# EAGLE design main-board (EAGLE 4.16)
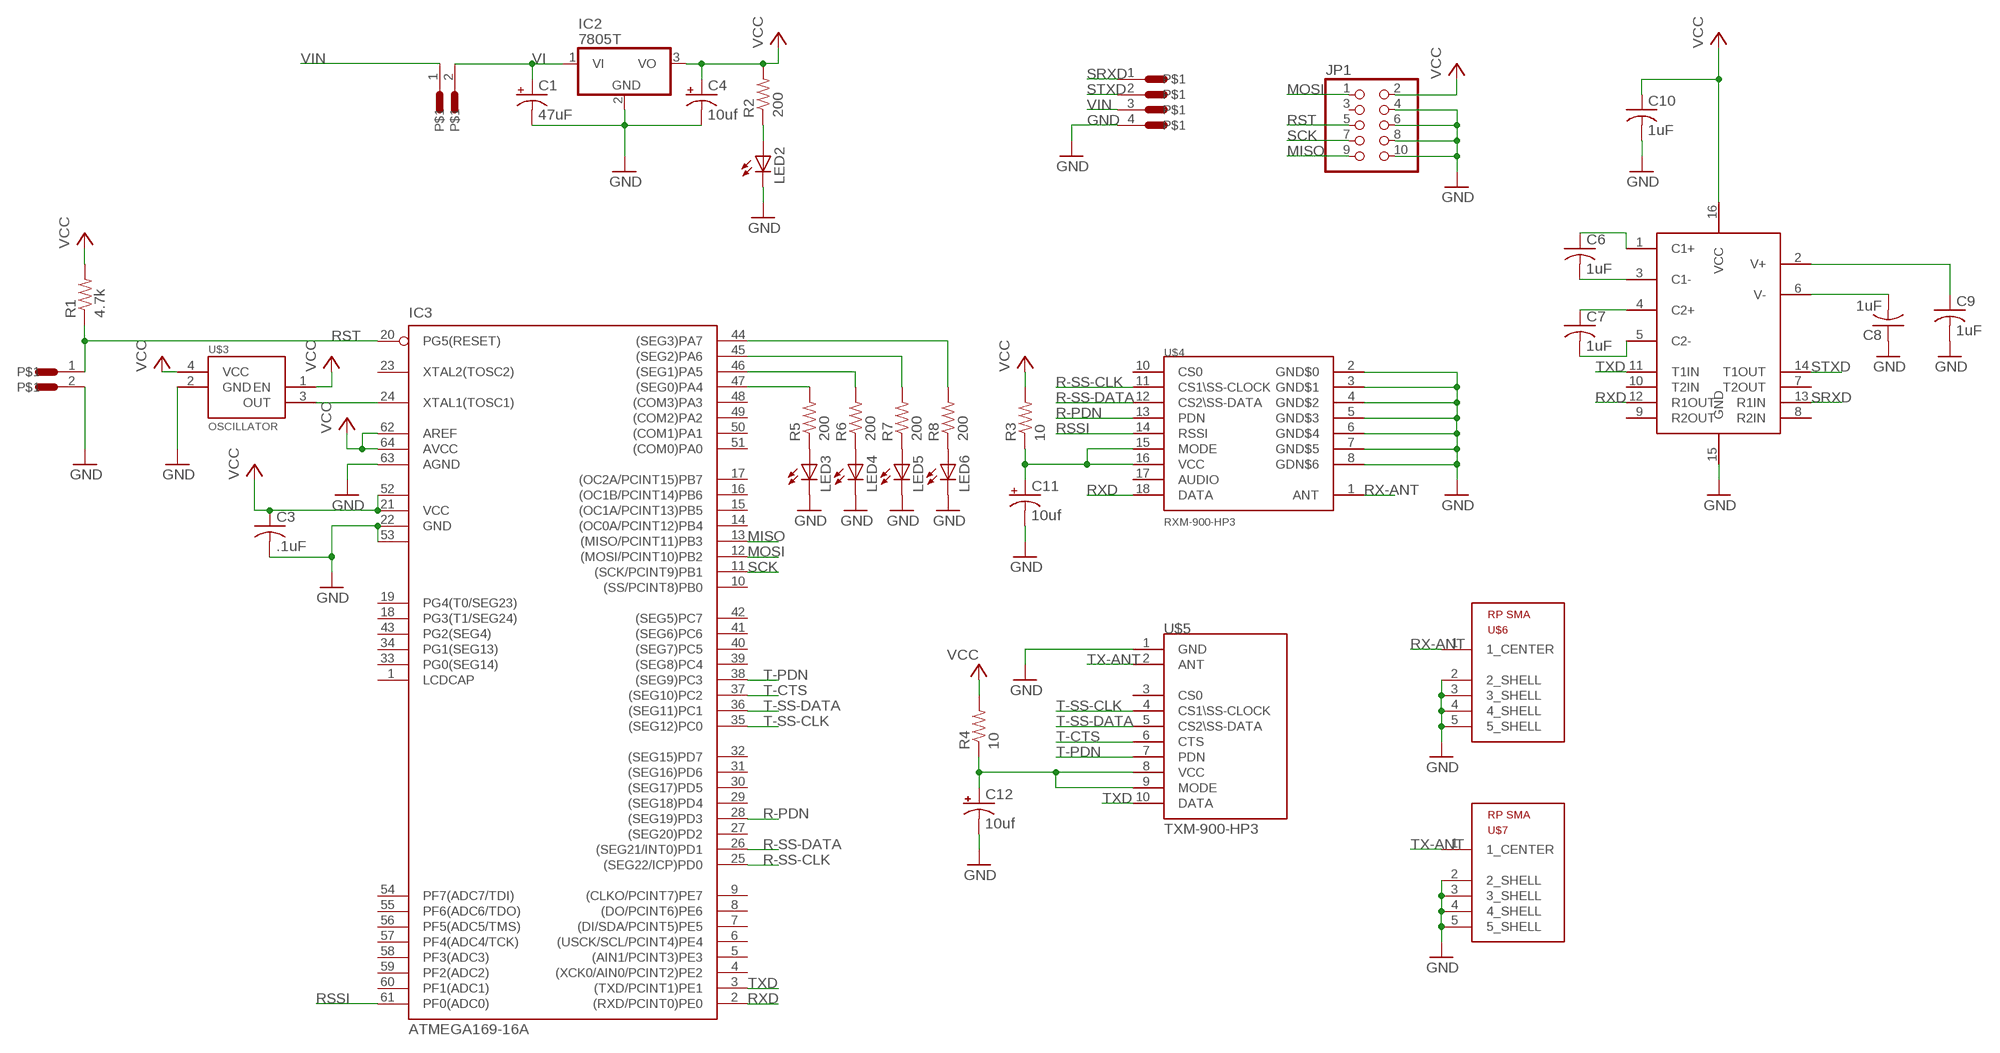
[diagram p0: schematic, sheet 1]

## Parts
C1  47uF  CPOL-USE  [PANASONIC_E]
C3  .1uF  C-USC0603  [C0603]
C4  10uf  CPOL-USB  [PANASONIC_B]
C6  1uF  C-USC0603  [C0603]
C7  1uF  C-USC0603  [C0603]
C8  1uF  C-USC0603  [C0603]
C9  1uF  C-USC0603  [C0603]
C10  1uF  C-USC0603  [C0603]
C11  10uf  CPOL-USB  [PANASONIC_B]
C12  10uf  CPOL-USB  [PANASONIC_B]
IC2  7805T  [TO220H]
IC3  ATMEGA169-16A  [TQFP64]
JP1  PINHD-2X5  [2X05]
LED2  LED5MM  [LED5MM]
LED3  LED5MM  [LED5MM]
LED4  LED5MM  [LED5MM]
LED5  LED5MM  [LED5MM]
LED6  LED5MM  [LED5MM]
R1  4.7k  R-US_R0603  [R0603]
R2  200  R-US_R0603  [R0603]
R3  10  R-US_R0603  [R0603]
R4  10  R-US_R0603  [R0603]
R5  200  R-US_R0603  [R0603]
R6  200  R-US_R0603  [R0603]
R7  200  R-US_R0603  [R0603]
R8  200  R-US_R0603  [R0603]
U$1  JST_PA_2  [JST_PA_2]
U$2  JST_PA_2  [JST_PA_2]
U$3  OSCILLATOR  [7X5MM]
U$4  RXM-900-HP3  [RXM-900-HP3]
U$5  TXM-900-HP3  [TXM-900-HP3]
U$6  RP_SMA_TH  [RPSMA_TH]
U$7  RP_SMA_TH  [RPSMA_TH]
U$8  JST_PA_4  [JST_PA_4]
U$9  MAX232-SO16  [SO16]

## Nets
GND: C1.- C3.2 C4.- C8.1 C9.2 C10.2 C11.- C12.- IC2.2(GND) IC3.22(GND) IC3.53(GND1) IC3.63(AGND) JP1.4 JP1.6 JP1.8 JP1.10 LED2.K(C) LED3.K(C) LED4.K(C) LED5.K(C) LED6.K(C) U$1.2 U$3.2(GND) U$4.2(GND$0) U$4.3(GND$1) U$4.4(GND$2) U$4.5(GND$3) U$4.6(GND$4) U$4.7(GND$5) U$4.8(GDN$6) U$5.1(GND) U$6.2(2_SHELL) U$6.3(3_SHELL) U$6.4(4_SHELL) U$6.5(5_SHELL) U$7.2(2_SHELL) U$7.3(3_SHELL) U$7.4(4_SHELL) U$7.5(5_SHELL) U$8.4 U$9.15(GND)
MISO: IC3.13((MISO/PCINT11)PB3) JP1.9
MOSI: IC3.12((MOSI/PCINT10)PB2) JP1.1
N$1: LED2.A R2.1
N$2: C6.1 U$9.1(C1+)
N$3: C6.2 U$9.3(C1-)
N$4: C7.1 U$9.4(C2+)
N$5: C7.2 U$9.5(C2-)
N$6: C9.1 U$9.2(V+)
N$7: C8.2 U$9.6(V-)
N$8: LED3.A R5.1
N$9: C12.+ R4.1 U$5.8(VCC) U$5.9(MODE)
N$10: LED4.A R6.1
N$11: LED5.A R7.1
N$12: C11.+ R3.1 U$4.15(MODE) U$4.16(VCC)
N$13: LED6.A R8.1
N$14: IC3.47((SEG0)PA4) R5.2
N$15: IC3.46((SEG1)PA5) R6.2
N$16: IC3.45((SEG2)PA6) R7.2
N$17: IC3.44((SEG3)PA7) R8.2
N$18: IC3.24(XTAL1(TOSC1)) U$3.3(OUT)
R-PDN: IC3.28((SEG19)PD3) U$4.13(PDN)
R-SS-CLK: IC3.25((SEG22/ICP)PD0) U$4.11(CS1\SS-CLOCK)
R-SS-DATA: IC3.26((SEG21/INT0)PD1) U$4.12(CS2\SS-DATA)
RSSI: IC3.61(PF0(ADC0)) U$4.14(RSSI)
RST: IC3.20(PG5(RESET)) JP1.5 R1.1 U$1.1
RX-ANT: U$4.1(ANT) U$6.1(1_CENTER)
RXD: IC3.2((RXD/PCINT0)PE0) U$4.18(DATA) U$9.12(R1OUT)
SCK: IC3.11((SCK/PCINT9)PB1) JP1.7
SRXD: U$8.1 U$9.13(R1IN)
STXD: U$8.2 U$9.14(T1OUT)
T-CTS: IC3.37((SEG10)PC2) U$5.6(CTS)
T-PDN: IC3.38((SEG9)PC3) U$5.7(PDN)
T-SS-CLK: IC3.35((SEG12)PC0) U$5.4(CS1\SS-CLOCK)
T-SS-DATA: IC3.36((SEG11)PC1) U$5.5(CS2\SS-DATA)
TX-ANT: U$5.2(ANT) U$7.1(1_CENTER)
TXD: IC3.3((TXD/PCINT1)PE1) U$5.10(DATA) U$9.11(T1IN)
VCC: C3.1 C4.+ C10.1 IC2.3(VO) IC3.21(VCC) IC3.52(VCC1) IC3.62(AREF) IC3.64(AVCC) JP1.2 R1.2 R2.2 R3.2 R4.2 U$3.1(EN) U$3.4(VCC) U$9.16(VCC)
VI: C1.+ IC2.1(VI) U$2.2
VIN: U$2.1 U$8.3
Unconnected: IC3.1(LCDCAP) IC3.4((XCK0/AIN0/PCINT2)PE2) IC3.5((AIN1/PCINT3)PE3) IC3.6((USCK/SCL/PCINT4)PE4) IC3.7((DI/SDA/PCINT5)PE5) IC3.8((DO/PCINT6)PE6) IC3.9((CLKO/PCINT7)PE7) IC3.10((SS/PCINT8)PB0) IC3.14((OC0A/PCINT12)PB4) IC3.15((OC1A/PCINT13)PB5) IC3.16((OC1B/PCINT14)PB6) IC3.17((OC2A/PCINT15)PB7) IC3.18(PG3(T1/SEG24)) IC3.19(PG4(T0/SEG23)) IC3.23(XTAL2(TOSC2)) IC3.27((SEG20)PD2) IC3.29((SEG18)PD4) IC3.30((SEG17)PD5) IC3.31((SEG16)PD6) IC3.32((SEG15)PD7) IC3.33(PG0(SEG14)) IC3.34(PG1(SEG13)) IC3.39((SEG8)PC4) IC3.40((SEG7)PC5) IC3.41((SEG6)PC6) IC3.42((SEG5)PC7) IC3.43(PG2(SEG4)) IC3.48((COM3)PA3) IC3.49((COM2)PA2) IC3.50((COM1)PA1) IC3.51((COM0)PA0) IC3.54(PF7(ADC7/TDI)) IC3.55(PF6(ADC6/TDO)) IC3.56(PF5(ADC5/TMS)) IC3.57(PF4(ADC4/TCK)) IC3.58(PF3(ADC3)) IC3.59(PF2(ADC2)) IC3.60(PF1(ADC1)) JP1.3 U$4.10(CS0) U$4.17(AUDIO) U$5.3(CS0) U$9.7(T2OUT) U$9.8(R2IN) U$9.9(R2OUT) U$9.10(T2IN)

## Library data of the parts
C1 C4 C11 C12 = rcl:CPOL-US: POLARIZED CAPACITOR, American symbol
C3 C6-C10 = rcl:C-US: CAPACITOR, American symbol
IC2 = linear:78*: Positive VOLTAGE REGULATOR Source: http://cache.national.com/ds/LM/LM78L05.pdf http://www.fairchildsemi.com/ds/LM/LM7805.pdf
IC3 = avr:ATMEGA169: MICROCONTROLLER 16 Kbytes FLASH 1 Kbytes SRAM 512 bytes EEPROM USART 8-channel 10 bit ADC 4x25 Segment LCD Driver
JP1 = pinhead:PINHD-2X5: PIN HEADER
LED2-LED6 = led:LED: LED
R1-R8 = rcl:R-US_: RESISTOR, American symbol
U$1 U$2 = jst_pa:JST_PA_2
U$3 = misc-personal:OSCILLATOR
U$4 = HP3:RXM-900-HP3
U$5 = HP3:TXM-900-HP3
U$6 U$7 = linx:RP_SMA_TH
U$8 = jst_pa:JST_PA_4
U$9 = max232:MAX232-SO16

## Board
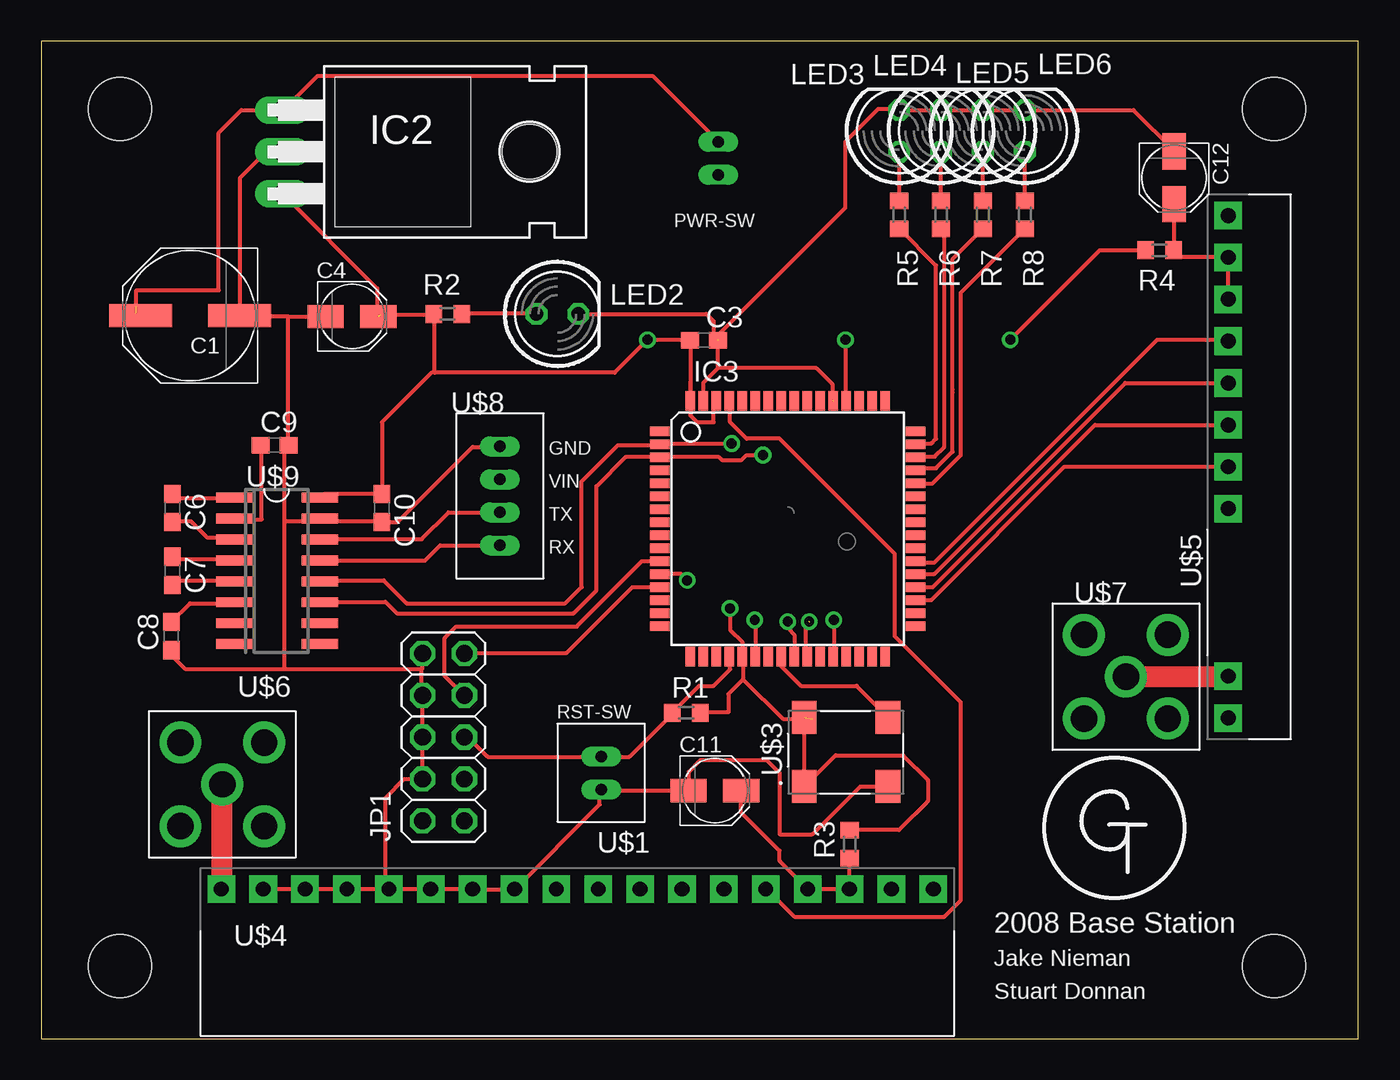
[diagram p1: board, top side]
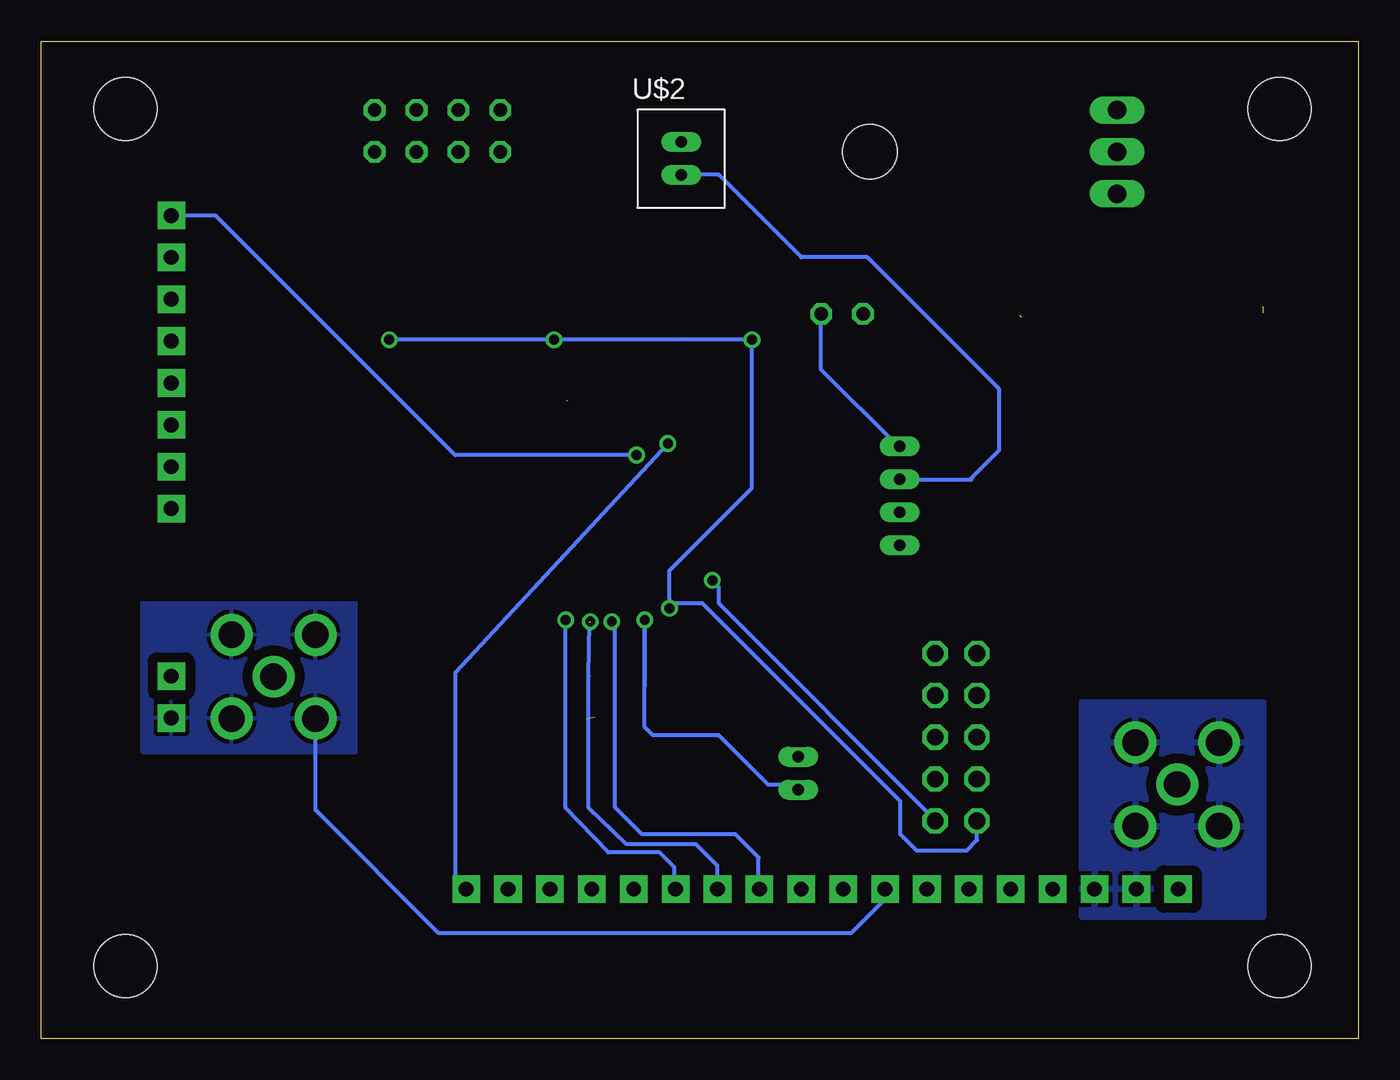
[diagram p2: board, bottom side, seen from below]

Size 79.87 x 60.49 mm. Coordinates in mm from the lower left corner, seen from the top.
Outline: 0,0 79.87,0 79.87,60.49 0,60.49 0,0
Copper layers (1*16): Top 0.035mm / dielectric 1.5mm / Bottom 0.035mm
Design rules "4pcb": minimum track width 6mil, minimum drill 15mil, track to track 6mil, track to pad 6mil, pad to pad 6mil, via to via 6mil, smd to smd 6mil, copper to edge 40mil, drill to drill 6mil, minimum pad ring 10mil, minimum via ring 8mil, stop-mask expansion 6mil, vias tented up to drill 0mil, thermal gap 10mil
Holes 3.82 mm at 4.77,56.39 4.77,4.39 74.77,4.39 74.77,56.39

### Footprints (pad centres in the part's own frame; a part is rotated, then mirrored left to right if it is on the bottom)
PANASONIC_E = smd 3.8 x 1.4: + 3,0; - -3,0
C0603 = smd 1.1 x 1: 1 -0.85,0; 2 0.85,0
PANASONIC_B = smd 2.2 x 1.4: + 1.6,0; - -1.6,0
TO220H = drill 1.118 long: 1 -2.54,-10.16; 2 0,-10.16; 3 2.54,-10.16 | hole 3.302: 0,4.826
TQFP64 = smd 1.194 x 0.559: 1 -7.76,5.905; 2 -7.76,5.118; 3 -7.76,4.331; 4 -7.76,3.543; 5 -7.76,2.756; 6 -7.76,1.968; 7 -7.76,1.181; 8 -7.76,0.394; 9 -7.76,-0.394; 10 -7.76,-1.181; 11 -7.76,-1.968; 12 -7.76,-2.756; 13 -7.76,-3.543; 14 -7.76,-4.331; 15 -7.76,-5.118; 16 -7.76,-5.905; 33 7.76,-5.905; 34 7.76,-5.118; 35 7.76,-4.331; 36 7.76,-3.543; 37 7.76,-2.756; 38 7.76,-1.968; 39 7.76,-1.181; 40 7.76,-0.394; 41 7.76,0.394; 42 7.76,1.181; 43 7.76,1.968; 44 7.76,2.756; 45 7.76,3.543; 46 7.76,4.331; 47 7.76,5.118; 48 7.76,5.905 | smd 0.559 x 1.194: 17 -5.905,-7.76; 18 -5.118,-7.76; 19 -4.331,-7.76; 20 -3.543,-7.76; 21 -2.756,-7.76; 22 -1.968,-7.76; 23 -1.181,-7.76; 24 -0.394,-7.76; 25 0.394,-7.76; 26 1.181,-7.76; 27 1.968,-7.76; 28 2.756,-7.76; 29 3.543,-7.76; 30 4.331,-7.76; 31 5.118,-7.76; 32 5.905,-7.76; 49 5.905,7.76; 50 5.118,7.76; 51 4.331,7.76; 52 3.543,7.76; 53 2.756,7.76; 54 1.968,7.76; 55 1.181,7.76; 56 0.394,7.76; 57 -0.394,7.76; 58 -1.181,7.76; 59 -1.968,7.76; 60 -2.756,7.76; 61 -3.543,7.76; 62 -4.331,7.76; 63 -5.118,7.76; 64 -5.905,7.76
2X05 = drill 1.016 octagon: 1 -5.08,-1.27; 2 -5.08,1.27; 3 -2.54,-1.27; 4 -2.54,1.27; 5 0,-1.27; 6 0,1.27; 7 2.54,-1.27; 8 2.54,1.27; 9 5.08,-1.27; 10 5.08,1.27
LED5MM = drill 0.813 octagon: A -1.27,0; K 1.27,0
R0603 = smd 1 x 1.1: 1 -0.85,0; 2 0.85,0
JST_PA_2 = drill 0.7 long: 1 13.35,0; 2 11.35,0
7X5MM = smd 1.5 x 2: 1 0,-4.2; 2 5.08,-4.2; 3 5.08,0; 4 0,0
RXM-900-HP3 = drill 0.9 pad 1.676 square: 1 0,0; 2 2.54,0; 3 5.08,0; 4 7.62,0; 5 10.16,0; 6 12.7,0; 7 15.24,0; 8 17.78,0; 9 20.32,0; 10 22.86,0; 11 25.4,0; 12 27.94,0; 13 30.48,0; 14 33.02,0; 15 35.56,0; 16 38.1,0; 17 40.64,0; 18 43.18,0
TXM-900-HP3 = drill 0.9 pad 1.676 square: 1 0,0; 2 2.54,0; 3 12.7,0; 4 15.24,0; 5 17.78,0; 6 20.32,0; 7 22.86,0; 8 25.4,0; 9 27.94,0; 10 30.48,0
RPSMA_TH = drill 1.6 pad 2.54 round: 1 0,0; 2 2.54,2.54; 3 2.54,-2.54; 4 -2.54,-2.54; 5 -2.54,2.54
JST_PA_4 = drill 0.7 long: 1 3,0; 2 1,0; 3 -1,0; 4 -3,0
SO16 = smd 0.6 x 2.2: 1 -4.445,-2.6; 2 -3.175,-2.6; 3 -1.905,-2.6; 4 -0.635,-2.6; 5 0.635,-2.6; 6 1.905,-2.6; 7 3.175,-2.6; 8 4.445,-2.6; 9 4.445,2.6; 10 3.175,2.6; 11 1.905,2.6; 12 0.635,2.6; 13 -0.635,2.6; 14 -1.905,2.6; 15 -3.175,2.6; 16 -4.445,2.6

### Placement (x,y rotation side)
C1  9.03,43.85 180 top
C3  40.19,42.35 0 top
C4  18.85,43.8 0 top
C6  7.95,32.18 270 top
C7  7.95,28.37 270 top
C8  7.89,24.41 90 top
C9  14.16,35.99 0 top
C10  20.65,32.18 270 top
C11  40.85,15.04 0 top
C12  68.7,52.21 270 top
IC2  24.79,53.78 270 top
IC3  45.27,30.92 0 top
JP1  24.39,18.28 90 top
LED2  31.3,43.95 0 top
LED3  52.03,55.05 90 top
LED4  54.57,55.05 90 top
LED5  57.11,55.05 90 top
LED6  59.65,55.05 90 top
R1  39.11,19.76 0 top
R2  24.65,43.95 180 top
R3  49.03,11.79 90 top
R4  67.81,47.81 180 top
R5  52.03,49.97 270 top
R6  54.57,49.97 270 top
R7  57.11,49.97 270 top
R8  59.65,49.97 270 top
U$1  33.96,3.74 90 top
U$2  41.06,65.74 270 bottom
U$3  46.27,19.49 0 top
U$4  10.92,9.07 0 top
U$5  71.98,19.44 90 top
U$6  10.98,15.42 180 top
U$7  65.78,21.95 0 top
U$8  27.82,32.92 270 top
U$9  14.3,28.37 270 top

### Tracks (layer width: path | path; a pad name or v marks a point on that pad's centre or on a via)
GND  (via drill 0.6)  (2 unrouted)
  Top 0.254: LED3.K 51.7,56.32 | 40.77,42.39 40.81,42.35 | IC3.63 40.17,38.7 40.17,39.79 41.07,40.69 | 47.97,38.74 47.97,39.69 46.97,40.69 41.07,40.69 | 23.62,9.04 23.57,8.99 | 23.62,9.04 U$4.6 21.15,9.07 21.08,9 | 23.62,9.04 23.65,9.07 U$4.7 26.09,9.07 | U$4.4 18.49,9.07 18.47,9.09 | U$4.4 U$4.5 21.08,9 | U$4.3 U$4.4 | U$4.3 15.97,9.09 | 14.77,31.39 16.75,31.39 U$9.15 16.77,31.41 16.77,31.39 20.59,31.39 C10.2 21.61,31.33 26.17,35.89 27.97,35.89 27.94,35.92 U$8.4 | 14.77,22.39 14.77,31.39 | C8.1 7.77,23.44 7.77,23.39 8.77,22.39 14.77,22.39 | 14.77,31.39 14.77,35.83 C9.2 14.97,35.99 14.97,43.8 | U$4.2 | U$4.2 U$4.3 | U$4.2 13.47,8.99 | LED2.K 40.33,43.95 40.77,43.51 40.77,42.39 | LED5.K 56.84,56.32 56.77,56.39 | LED5.K LED6.K 59.7,56.32 59.77,56.39 59.84,56.32 66.24,56.32 68.7,53.86 C12.- | LED5.K 54.84,56.32 54.77,56.39 54.7,56.32 LED4.K LED3.K | LED3.K 51.84,56.32 51.77,56.39 | 40.77,42.39 48.77,50.39 48.77,54.39 50.77,56.39 51.77,56.39 | 51.77,56.39 51.96,56.39 LED3.K | 40.77,42.39 41,42.39 | 33.92,15.04 U$1.2 | 33.92,15.04 C11.- 39.25,15.01 39.27,14.99 39.27,16.18 39.98,16.89 43.99,16.89 44.77,16.11 44.77,12.39 46.77,12.39 49.67,15.29 U$3.2 | 33.92,15.04 33.87,14.99 33.87,14.19 28.7,9.02 | 26.09,9.07 26.07,9.09 | 26.09,9.07 26.1,9.06 U$4.8 28.7,9.02 | 28.7,9.02 28.67,8.99 | JP1.6 23.12,18.24 23.07,18.19 | JP1.6 JP1.8 23.1,20.82 23.07,20.79 23.07,22.39 | JP1.6 23.12,18.04 23.17,17.99 23.12,17.94 JP1.4 22.02,15.74 20.87,14.59 20.87,9.19 21.07,8.99 21.08,9 | 23.07,22.39 14.77,22.39 | JP1.10 23.12,22.44 23.07,22.39 | 12.07,43.79 12.03,43.83 C1.- 11.98,43.8 | 12.07,43.79 12.07,52.22 13.63,53.78 IC2.2 | 12.07,43.79 12.17,43.69
  Top 0.254: 14.97,43.8 11.98,43.8 | 14.97,43.8 C4.- | 11.98,43.8 11.97,43.79 | C3.2 41.04,40.72 41.07,40.69 | IC3.22 43.3,25.36 v43.27,25.39
  Bottom 0.254: 43.27,21.39 v43.27,25.39 43.27,18.89 42.77,18.39 38.77,18.39 35.77,15.39 34.27,15.39 U$1.2 | U$8.4 27.84,35.92 27.87,35.89 32.57,40.59 LED2.K | U$7.4 63.24,13.86 55.77,6.39 30.77,6.39 28.77,8.39 28.77,9.39 28.7,9.32 U$4.8
  pour Bottom (isolate 0.61): 60.77,26.39 73.77,26.39 73.77,17.39 60.77,17.39
  pour Bottom (isolate 0.61): 5.77,20.39 16.77,20.39 16.77,7.39 5.77,7.39
MISO
  Top 0.254: IC3.13 35.86,27.38 31.87,23.39 25.87,23.39 25.67,23.19 25.66,23.2 JP1.9
MOSI  (via drill 0.6)
  Top 0.254: v39.17,27.79 38.77,28.19 37.77,28.19 37.67,28.09 37.6,28.16 IC3.12
  Bottom 0.254: JP1.1 25.66,13.28 38.77,26.39 38.77,27.39 v39.17,27.79
N$1
  Top 0.254: R2.1 25.47,43.98 25.47,43.99 29.99,43.99 LED2.A
N$2
  Top 0.254: C6.1 7.97,33.01 7.97,32.79 11.67,32.79 U$9.1
N$3
  Top 0.254: U$9.3 11.58,30.39 10.07,30.39 9.07,31.39 7.89,31.39 | 7.89,31.39 7.77,31.39 | C6.2 7.89,31.39
N$4
  Top 0.254: C7.1 8.08,29.09 11.62,29.09 U$9.4
N$5
  Top 0.254: C7.2 8.07,27.64 8.07,27.79 11.64,27.79 U$9.5
N$6
  Top 0.254: C9.1 13.37,35.53 13.37,31.49 11.67,31.49 11.67,31.52 U$9.2
N$7
  Top 0.254: U$9.6 11.77,26.39 9.02,26.39 C8.2
N$8
  Top 0.254: R5.1 52.07,50.79 | R5.1 | LED3.A R5.1
N$9
  Top 0.254: 68.66,47.5 68.77,47.39 71.77,47.39 71.78,47.38 U$5.9 71.98,44.8 | 68.66,47.5 R4.1 68.67,47.79 68.7,47.82 C12.+ | 68.66,47.5 68.65,47.51 | U$5.8 71.98,44.8 | 71.98,44.8 71.97,44.79
N$10
  Top 0.254: 54.48,53.78 54.47,53.79 | 54.48,53.78 LED4.A | R6.1 54.57,53.69 54.48,53.78
N$11
  Top 0.254: R7.1 57.17,50.89 57.11,50.95 LED5.A
N$12
  Top 0.254: C11.+ 42.45,13.71 44.77,11.39 44.77,10.79 U$4.15 48.95,9.07 48.97,9.09 48.99,9.07 U$4.16 49.02,10.84 48.97,10.89 R3.1
N$13
  Top 0.254: R8.1 59.65,50.87 59.67,50.89 59.65,50.91 LED6.A
N$14
  Top 0.254: IC3.47 53.03,36.09 53.97,36.09 54.27,36.39 54.27,46.88 R5.2
N$15
  Top 0.254: 53.17,35.29 53.03,35.15 IC3.46 53.07,35.29 54.17,35.29 54.77,35.89 54.77,48.89 54.57,49.09 R6.2
N$16
  Top 0.254: 55.27,39.19 55.27,35.59 54.27,34.59 53.17,34.59 53.04,34.46 IC3.45 | 55.27,39.19 55.27,39.39 | R7.2 55.27,47.28 55.27,39.19
N$17
  Top 0.254: 52.97,33.59 53.03,33.65 IC3.44 54.06,33.68 55.77,35.39 55.77,39.39 | 55.77,39.39 55.77,39.79 | R8.2 55.77,45.24 55.77,39.39
N$18
  Top 0.254: U$3.3 49.45,21.39 46.07,21.39 44.87,22.59 44.87,22.99 44.97,23.09 44.9,23.16 IC3.24
R-PDN  (via drill 0.6)
  Top 0.254: IC3.28 48.07,23.2 v48.07,25.39
  Bottom 0.254: U$4.13 41.42,9.09 41.47,9.09 41.47,10.39 42.37,11.29 45.47,11.29 48.07,13.99 v48.07,25.39
R-SS-CLK  (via drill 0.6)
  Top 0.254: IC3.25 45.67,24.49 45.27,24.89 v45.27,25.29
  Bottom 0.254: 36.37,9.02 36.37,8.99 | U$4.11 36.37,9.02 | 36.37,9.02 36.37,10.99 37.77,12.39 43.43,12.39 45.07,14.03 45.07,25.09 v45.27,25.29
R-SS-DATA  (via drill 0.6)  (1 unrouted)
  Top 0.254: IC3.26 46.37,23.24 46.37,25.19 46.47,25.29 v46.57,25.29
  Bottom 0.254: U$4.12 38.87,10.49 40.17,11.79 44.37,11.79 46.67,13.99 46.67,21.99 46.62,25.24
RSSI
  Top 0.254: IC3.61 41.77,38.64 41.77,37.39 42.77,36.39 44.77,36.39 51.77,29.39 51.77,24.39 55.77,20.39 55.77,8.39 54.77,7.39 45.67,7.39 43.97,9.09 U$4.14
RST
  Top 0.254: 41.77,23.2 41.77,23.39 | 41.77,23.2 IC3.20 | 41.77,23.2 41.77,22.39 40.77,21.39 39.89,21.39 R1.1 38.26,19.7 38.27,19.69 35.67,17.09 U$1.1 27.07,17.09 25.77,18.39 JP1.5
RX-ANT
  Top 1.27: U$4.1 10.97,9.07 U$6.1
RXD  (via drill 0.6)
  Top 0.254: v41.87,36.09 37.56,36.09 IC3.2 37.56,35.99 | 16.95,27.79 U$9.12 16.9,27.82 16.97,27.89 17.07,27.79 20.77,27.79 22.17,26.39 31.77,26.39 32.77,27.39 32.77,33.79 34.97,35.99 37.56,35.99 | 37.56,35.99 37.57,35.99
  Bottom 0.254: v41.87,36.09 54.77,22.19 54.77,9.79 54.07,9.09 U$4.18 53.78,9.39 53.77,9.39
SCK
  Top 0.254: IC3.11 36.43,28.95 32.47,24.99 25.17,24.99 24.47,24.29 24.47,21.99 25.66,20.8 | 25.66,20.8 25.67,20.79 | 25.66,20.8 JP1.7
SRXD
  Top 0.254: U$8.1 24.2,29.92 23.27,28.99 16.97,28.99 16.95,29 U$9.13
STXD
  Top 0.254: U$8.2 24.7,31.92 23.07,30.29 17.07,30.29 16.97,30.19 16.9,30.26 U$9.14
T-CTS
  Top 0.254: IC3.37 53.06,28.19 54.17,28.19 65.74,39.76 U$5.6
T-PDN
  Top 0.254: IC3.38 53.07,28.91 53.07,28.89 54.17,28.89 67.67,42.39 71.89,42.39 U$5.7
T-SS-CLK
  Top 0.254: IC3.35 53.97,26.59 62.06,34.68 U$5.4
T-SS-DATA
  Top 0.254: IC3.36 53.04,27.39 54.07,27.39 63.9,37.22 U$5.5
TX-ANT
  Top 1.27: U$5.2 | U$5.2 | U$7.1 71.97,21.95 U$5.2
TXD  (via drill 0.6)
  Top 0.254: 37.55,35.29 IC3.3 37.47,35.29 | 37.55,35.29 37.65,35.39 | 16.97,26.59 16.97,26.54 U$9.11 16.97,26.39 17.07,26.49 20.87,26.49 21.57,25.79 32.27,25.79 33.67,27.19 33.67,33.49 35.47,35.29 37.47,35.29 | v43.77,35.39 42.77,35.39 42.47,35.09 41.27,35.09 41.07,35.29 37.47,35.29 | 37.47,35.29 37.55,35.29
  Bottom 0.254: U$5.10 69.3,49.92 54.77,35.39 v43.77,35.39
VCC  (via drill 0.6)  (3 unrouted)
  Top 0.254: IC3.64 39.37,38.59 | IC3.64 39.36,37.8 39.77,37.39 40.77,37.39 40.77,38.39 40.97,38.59 40.94,38.62 IC3.62 | IC3.64 39.37,42.32 C3.1 39.37,42.38 39.37,42.39 v36.77,42.39 34.77,40.39 23.86,40.39 | 48.77,38.64 48.77,38.39 | 48.77,38.64 IC3.52 | v48.77,42.39 48.77,38.64 | U$3.4 U$3.1 48.17,17.19 52.27,17.19 53.77,15.69 53.77,14.39 52.03,12.65 R3.2 | 42.57,21.79 42.57,23.1 IC3.21 42.51,24.05 41.77,24.79 v41.77,26.09 | 42.57,21.79 44.97,19.39 46.77,19.39 | 23.87,43.89 R2.2 | 23.87,43.89 23.83,43.85 | 23.86,40.39 23.67,40.39 20.67,37.39 20.67,32.89 20.65,32.91 C10.1 17.21,33.03 16.97,32.79 16.95,32.81 U$9.16 | IC3.64 39.37,39.79 | R4.2 64.19,47.81 v58.77,42.39 | 42.57,21.79 41.67,20.89 41.67,19.79 39.99,19.79 R1.2 | C4.+ 20.37,43.79 20.37,45.5 IC2.3 | 23.87,43.89 23.77,43.92 R2.2 | 23.87,43.89 20.54,43.89 | 23.86,43.98 23.83,43.95 R2.2 | 23.86,40.39 23.86,43.98 | 23.86,43.98 23.87,43.99
  Bottom 0.254: v58.77,42.39 v48.77,42.39 v36.77,42.39 36.77,33.39 41.77,28.39 v41.77,26.09 | v41.77,26.09 41.72,26.14 | JP1.2 23.12,12.04 23.77,11.39 26.77,11.39 27.77,12.39 27.77,14.39 39.77,26.39 41.47,26.39 v41.77,26.09
VI  (1 unrouted)
  Top 0.254: 14.7,56.39 14.63,56.39 IC2.1 | U$2.2 37.06,58.39 16.77,58.39 14.77,56.39 14.7,56.39 | IC2.1 14.7,56.39 | IC2.1 12.14,56.32 10.77,54.95 10.77,45.39 5.77,45.39 5.77,43.99 5.97,43.79 C1.+ | 5.77,43.39 5.77,44.39
VIN
  Bottom 0.254: U$8.3 27.8,33.92 27.77,33.89 23.47,33.89 23.47,33.99 21.77,35.69 21.77,39.39 29.77,47.39 33.77,47.39 38.77,52.39 U$2.1

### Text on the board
tPlace: 2008 Base Station | Jake Nieman | Stuart Donnan
tNames: PWR-SW | GND | VIN | TX | RX | RST-SW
